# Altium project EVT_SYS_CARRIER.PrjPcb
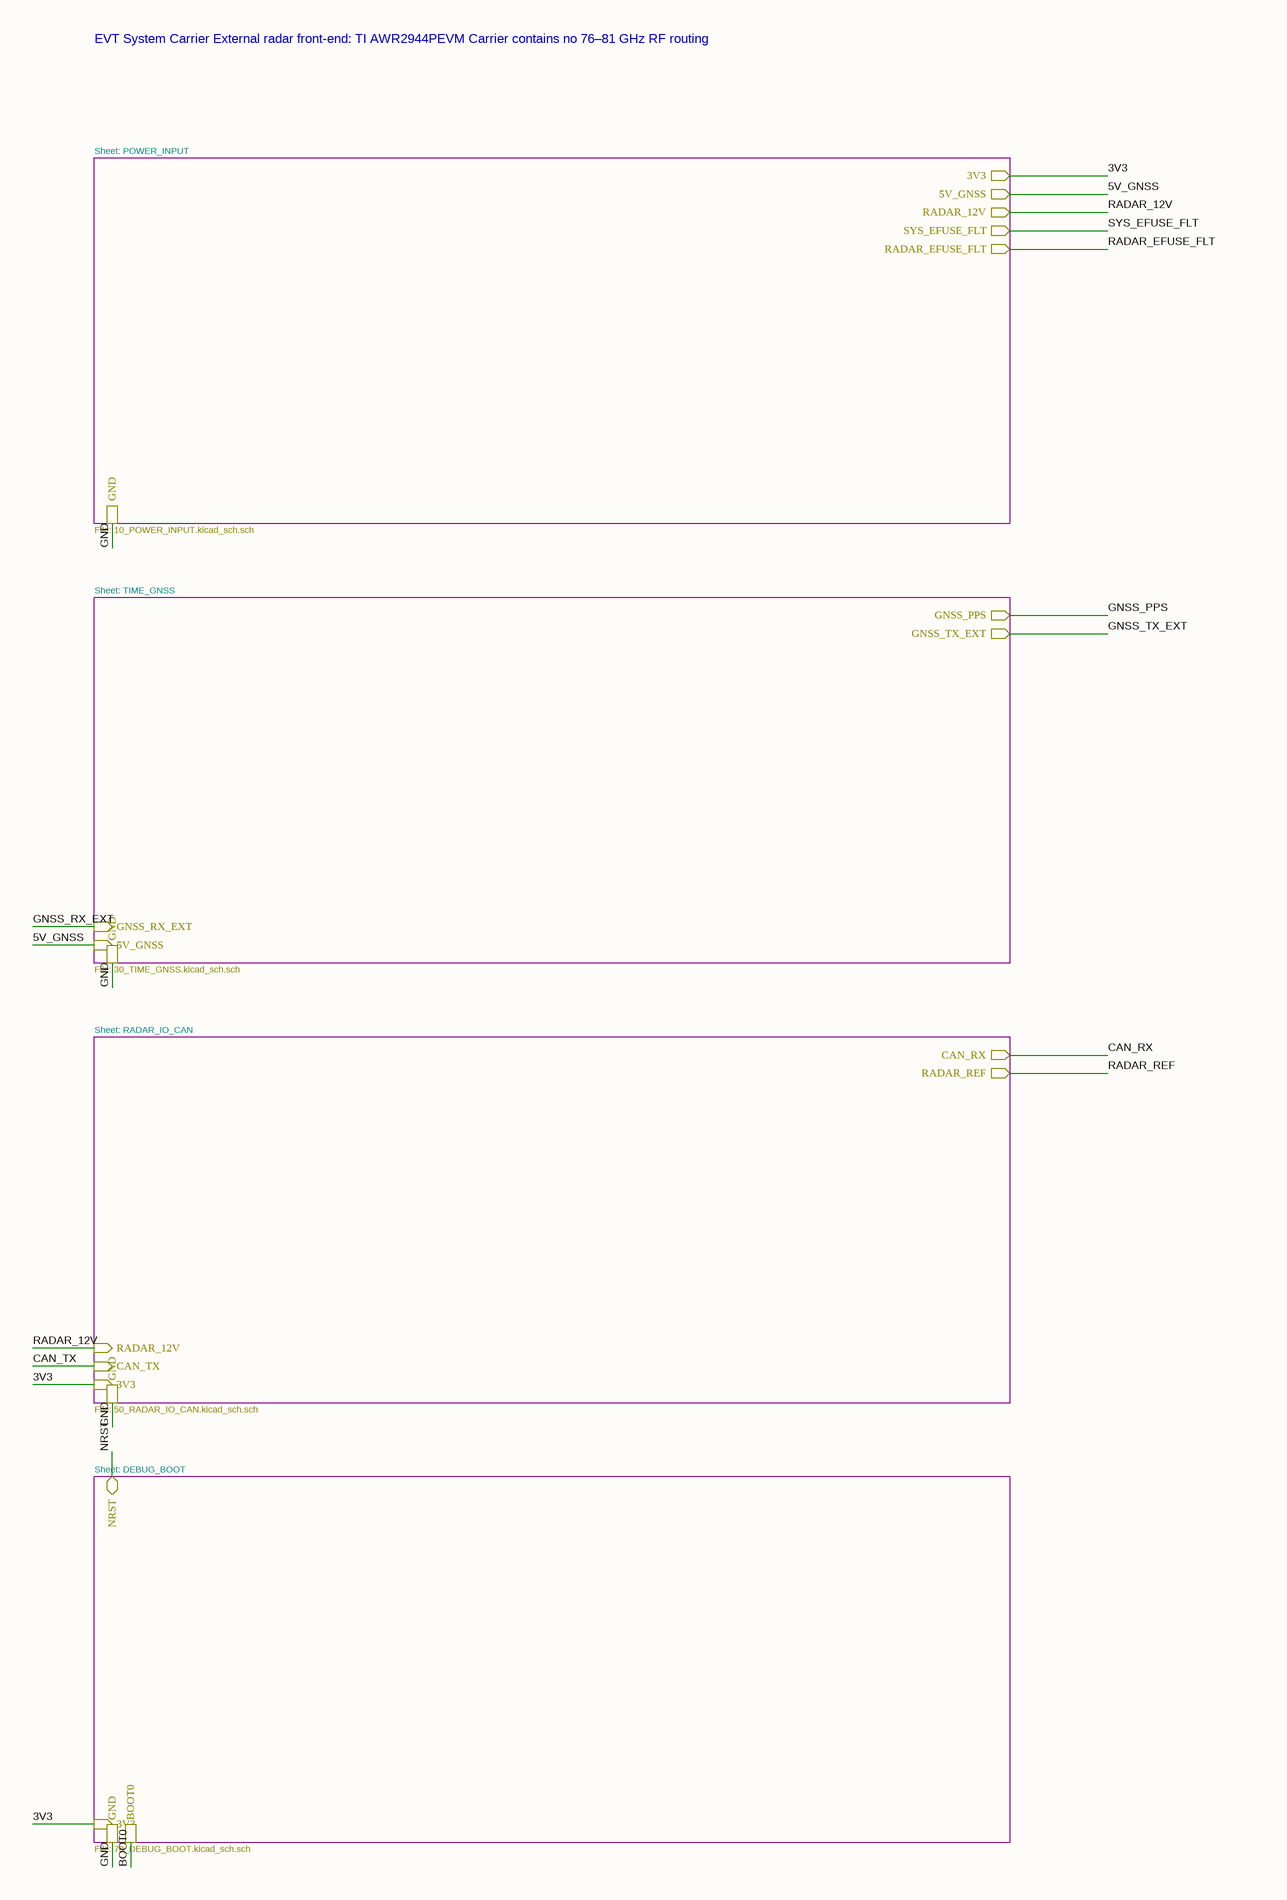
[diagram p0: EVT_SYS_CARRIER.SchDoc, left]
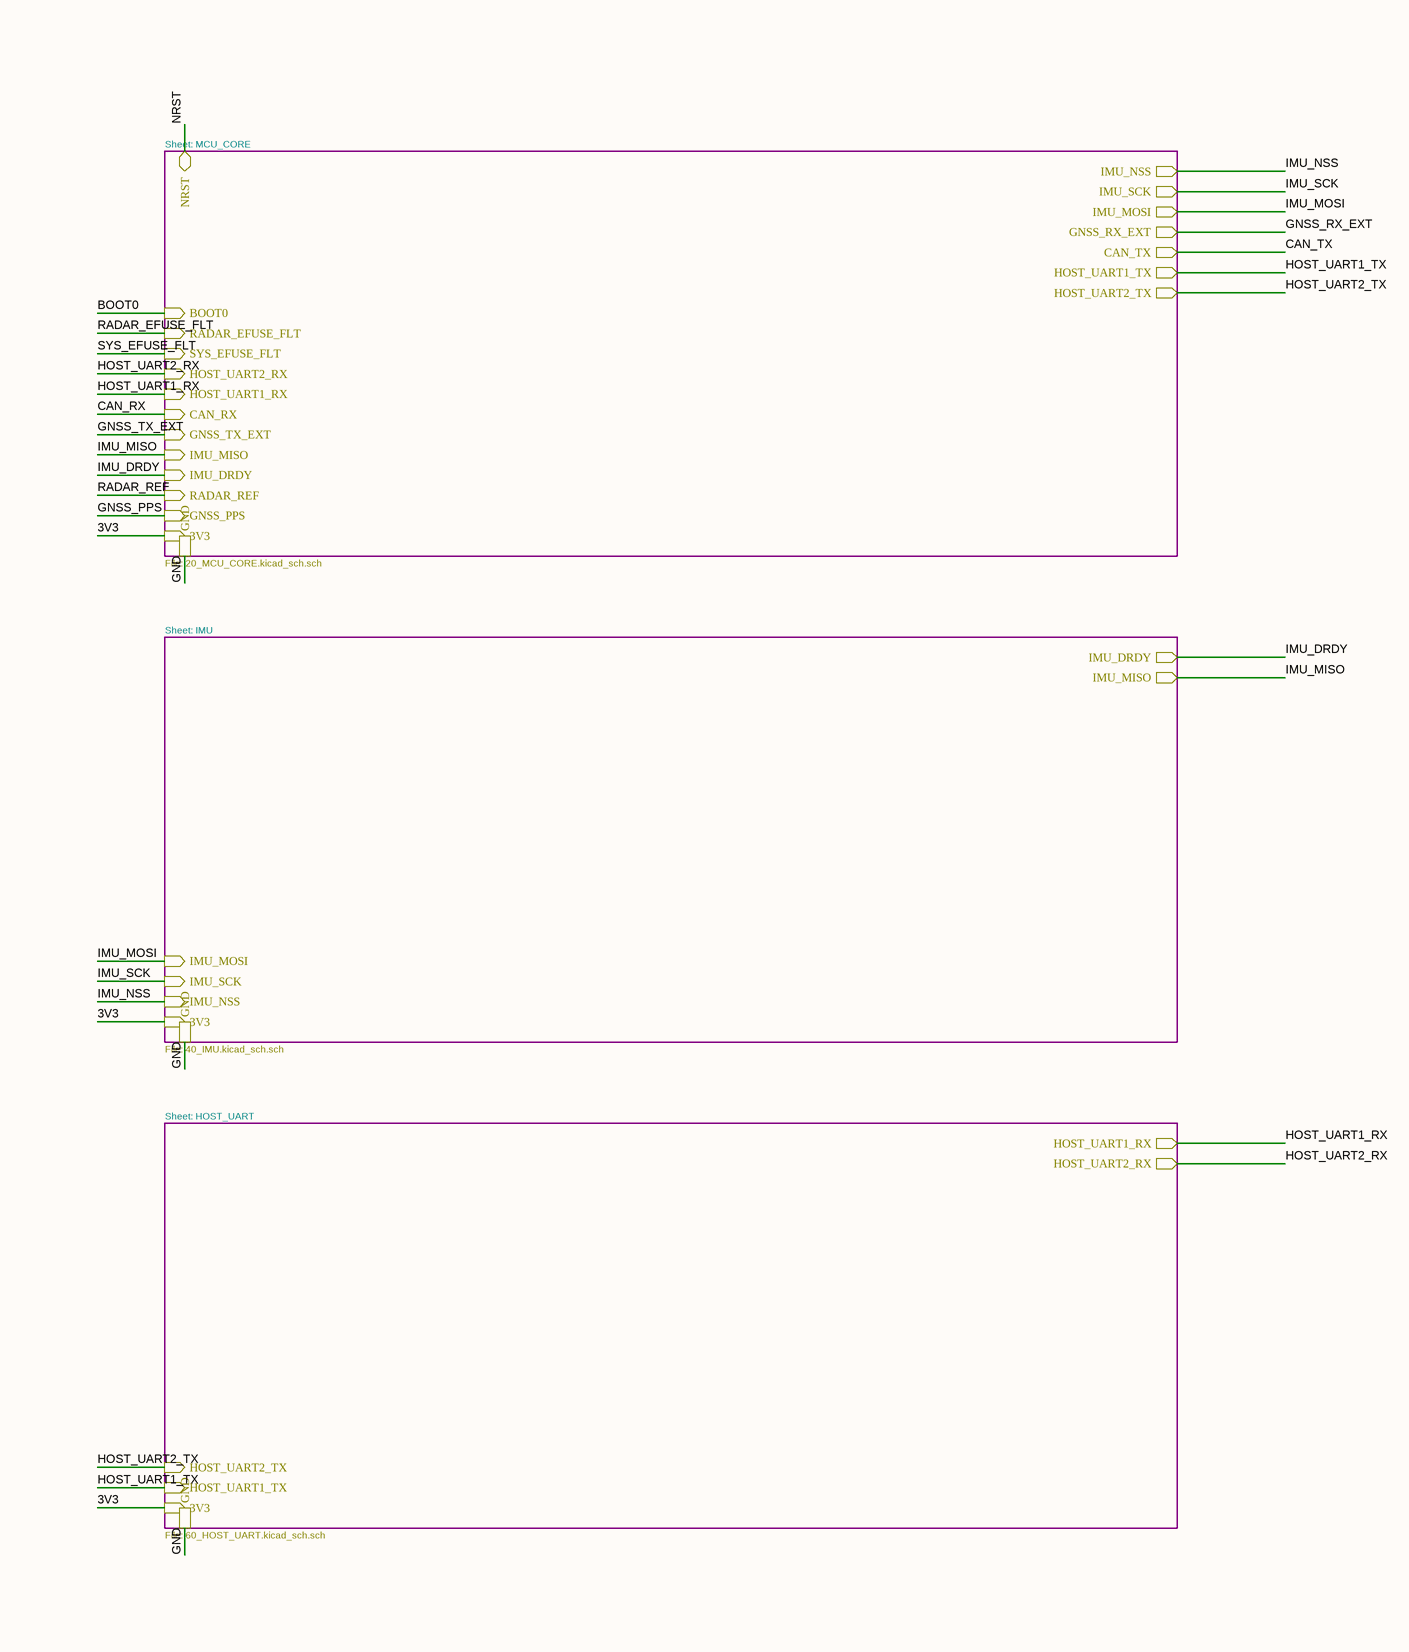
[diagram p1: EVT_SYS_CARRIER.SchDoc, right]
8 sheets, 112 parts. Net scope: hierarchical (ports join the sheet entries above them; power ports are global).
Board file: EVT_SYS_CARRIER.PcbDoc
Sheets:
  EVT_SYS_CARRIER.SchDoc
    POWER_INPUT = 10_POWER_INPUT.SchDoc
    MCU_CORE = 20_MCU_CORE.SchDoc
    TIME_GNSS = 30_TIME_GNSS.SchDoc
    IMU = 40_IMU.SchDoc
    RADAR_IO_CAN = 50_RADAR_IO_CAN.SchDoc
    HOST_UART = 60_HOST_UART.SchDoc
    DEBUG_BOOT = 70_DEBUG_BOOT.SchDoc

## Sheet EVT_SYS_CARRIER.SchDoc
size 594 x 420 mm

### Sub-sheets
DEBUG_BOOT = 70_DEBUG_BOOT.SchDoc: 3V3 (in), GND, NRST (bidir), BOOT0
HOST_UART = 60_HOST_UART.SchDoc: 3V3 (in), GND, HOST_UART1_TX (in), HOST_UART1_RX (out), HOST_UART2_TX (in), HOST_UART2_RX (out)
IMU = 40_IMU.SchDoc: 3V3 (in), GND, IMU_DRDY (out), IMU_NSS (in), IMU_SCK (in), IMU_MISO (out), IMU_MOSI (in)
MCU_CORE = 20_MCU_CORE.SchDoc: 3V3 (in), GND, GNSS_PPS (in), RADAR_REF (in), IMU_DRDY (in), IMU_NSS (out), IMU_SCK (out), IMU_MISO (in), IMU_MOSI (out), GNSS_RX_EXT (out), GNSS_TX_EXT (in), CAN_RX (in), CAN_TX (out), HOST_UART1_TX (out), HOST_UART1_RX (in), HOST_UART2_TX (out), HOST_UART2_RX (in), SYS_EFUSE_FLT (in), RADAR_EFUSE_FLT (in), NRST (bidir), BOOT0 (in)
POWER_INPUT = 10_POWER_INPUT.SchDoc: 3V3 (out), 5V_GNSS (out), RADAR_12V (out), SYS_EFUSE_FLT (out), RADAR_EFUSE_FLT (out), GND
RADAR_IO_CAN = 50_RADAR_IO_CAN.SchDoc: 3V3 (in), GND, CAN_TX (in), CAN_RX (out), RADAR_REF (out), RADAR_12V (in)
TIME_GNSS = 30_TIME_GNSS.SchDoc: 5V_GNSS (in), GND, GNSS_PPS (out), GNSS_TX_EXT (out), GNSS_RX_EXT (in)

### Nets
3V3: sheet POWER_INPUT/3V3, sheet MCU_CORE/3V3, sheet IMU/3V3, sheet RADAR_IO_CAN/3V3, sheet HOST_UART/3V3, sheet DEBUG_BOOT/3V3
5V_GNSS: sheet POWER_INPUT/5V_GNSS, sheet TIME_GNSS/5V_GNSS
BOOT0: sheet MCU_CORE/BOOT0, sheet DEBUG_BOOT/BOOT0
CAN_RX: sheet MCU_CORE/CAN_RX, sheet RADAR_IO_CAN/CAN_RX
CAN_TX: sheet MCU_CORE/CAN_TX, sheet RADAR_IO_CAN/CAN_TX
GND: sheet POWER_INPUT/GND, sheet MCU_CORE/GND, sheet TIME_GNSS/GND, sheet IMU/GND, sheet RADAR_IO_CAN/GND, sheet HOST_UART/GND, sheet DEBUG_BOOT/GND
GNSS_PPS: sheet MCU_CORE/GNSS_PPS, sheet TIME_GNSS/GNSS_PPS
GNSS_RX_EXT: sheet MCU_CORE/GNSS_RX_EXT, sheet TIME_GNSS/GNSS_RX_EXT
GNSS_TX_EXT: sheet MCU_CORE/GNSS_TX_EXT, sheet TIME_GNSS/GNSS_TX_EXT
HOST_UART1_RX: sheet MCU_CORE/HOST_UART1_RX, sheet HOST_UART/HOST_UART1_RX
HOST_UART1_TX: sheet MCU_CORE/HOST_UART1_TX, sheet HOST_UART/HOST_UART1_TX
HOST_UART2_RX: sheet MCU_CORE/HOST_UART2_RX, sheet HOST_UART/HOST_UART2_RX
HOST_UART2_TX: sheet MCU_CORE/HOST_UART2_TX, sheet HOST_UART/HOST_UART2_TX
IMU_DRDY: sheet MCU_CORE/IMU_DRDY, sheet IMU/IMU_DRDY
IMU_MISO: sheet MCU_CORE/IMU_MISO, sheet IMU/IMU_MISO
IMU_MOSI: sheet MCU_CORE/IMU_MOSI, sheet IMU/IMU_MOSI
IMU_NSS: sheet MCU_CORE/IMU_NSS, sheet IMU/IMU_NSS
IMU_SCK: sheet MCU_CORE/IMU_SCK, sheet IMU/IMU_SCK
NRST: sheet MCU_CORE/NRST, sheet DEBUG_BOOT/NRST
RADAR_12V: sheet POWER_INPUT/RADAR_12V, sheet RADAR_IO_CAN/RADAR_12V
RADAR_EFUSE_FLT: sheet POWER_INPUT/RADAR_EFUSE_FLT, sheet MCU_CORE/RADAR_EFUSE_FLT
RADAR_REF: sheet MCU_CORE/RADAR_REF, sheet RADAR_IO_CAN/RADAR_REF
SYS_EFUSE_FLT: sheet POWER_INPUT/SYS_EFUSE_FLT, sheet MCU_CORE/SYS_EFUSE_FLT

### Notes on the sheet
- EVT System Carrier
  External radar front-end: TI AWR2944PEVM
  Carrier contains no 76–81 GHz RF routing
- Sheet: POWER_INPUT
- Sheet: MCU_CORE
- File: 10_POWER_INPUT.kicad_sch.sch
- File: 20_MCU_CORE.kicad_sch.sch
- Sheet: TIME_GNSS
- Sheet: IMU
- File: 30_TIME_GNSS.kicad_sch.sch
- File: 40_IMU.kicad_sch.sch
- Sheet: RADAR_IO_CAN
- Sheet: HOST_UART
- File: 50_RADAR_IO_CAN.kicad_sch.sch
- File: 60_HOST_UART.kicad_sch.sch
- Sheet: DEBUG_BOOT
- File: 70_DEBUG_BOOT.kicad_sch.sch

## Sheet 10_POWER_INPUT.SchDoc
size 420 x 297 mm
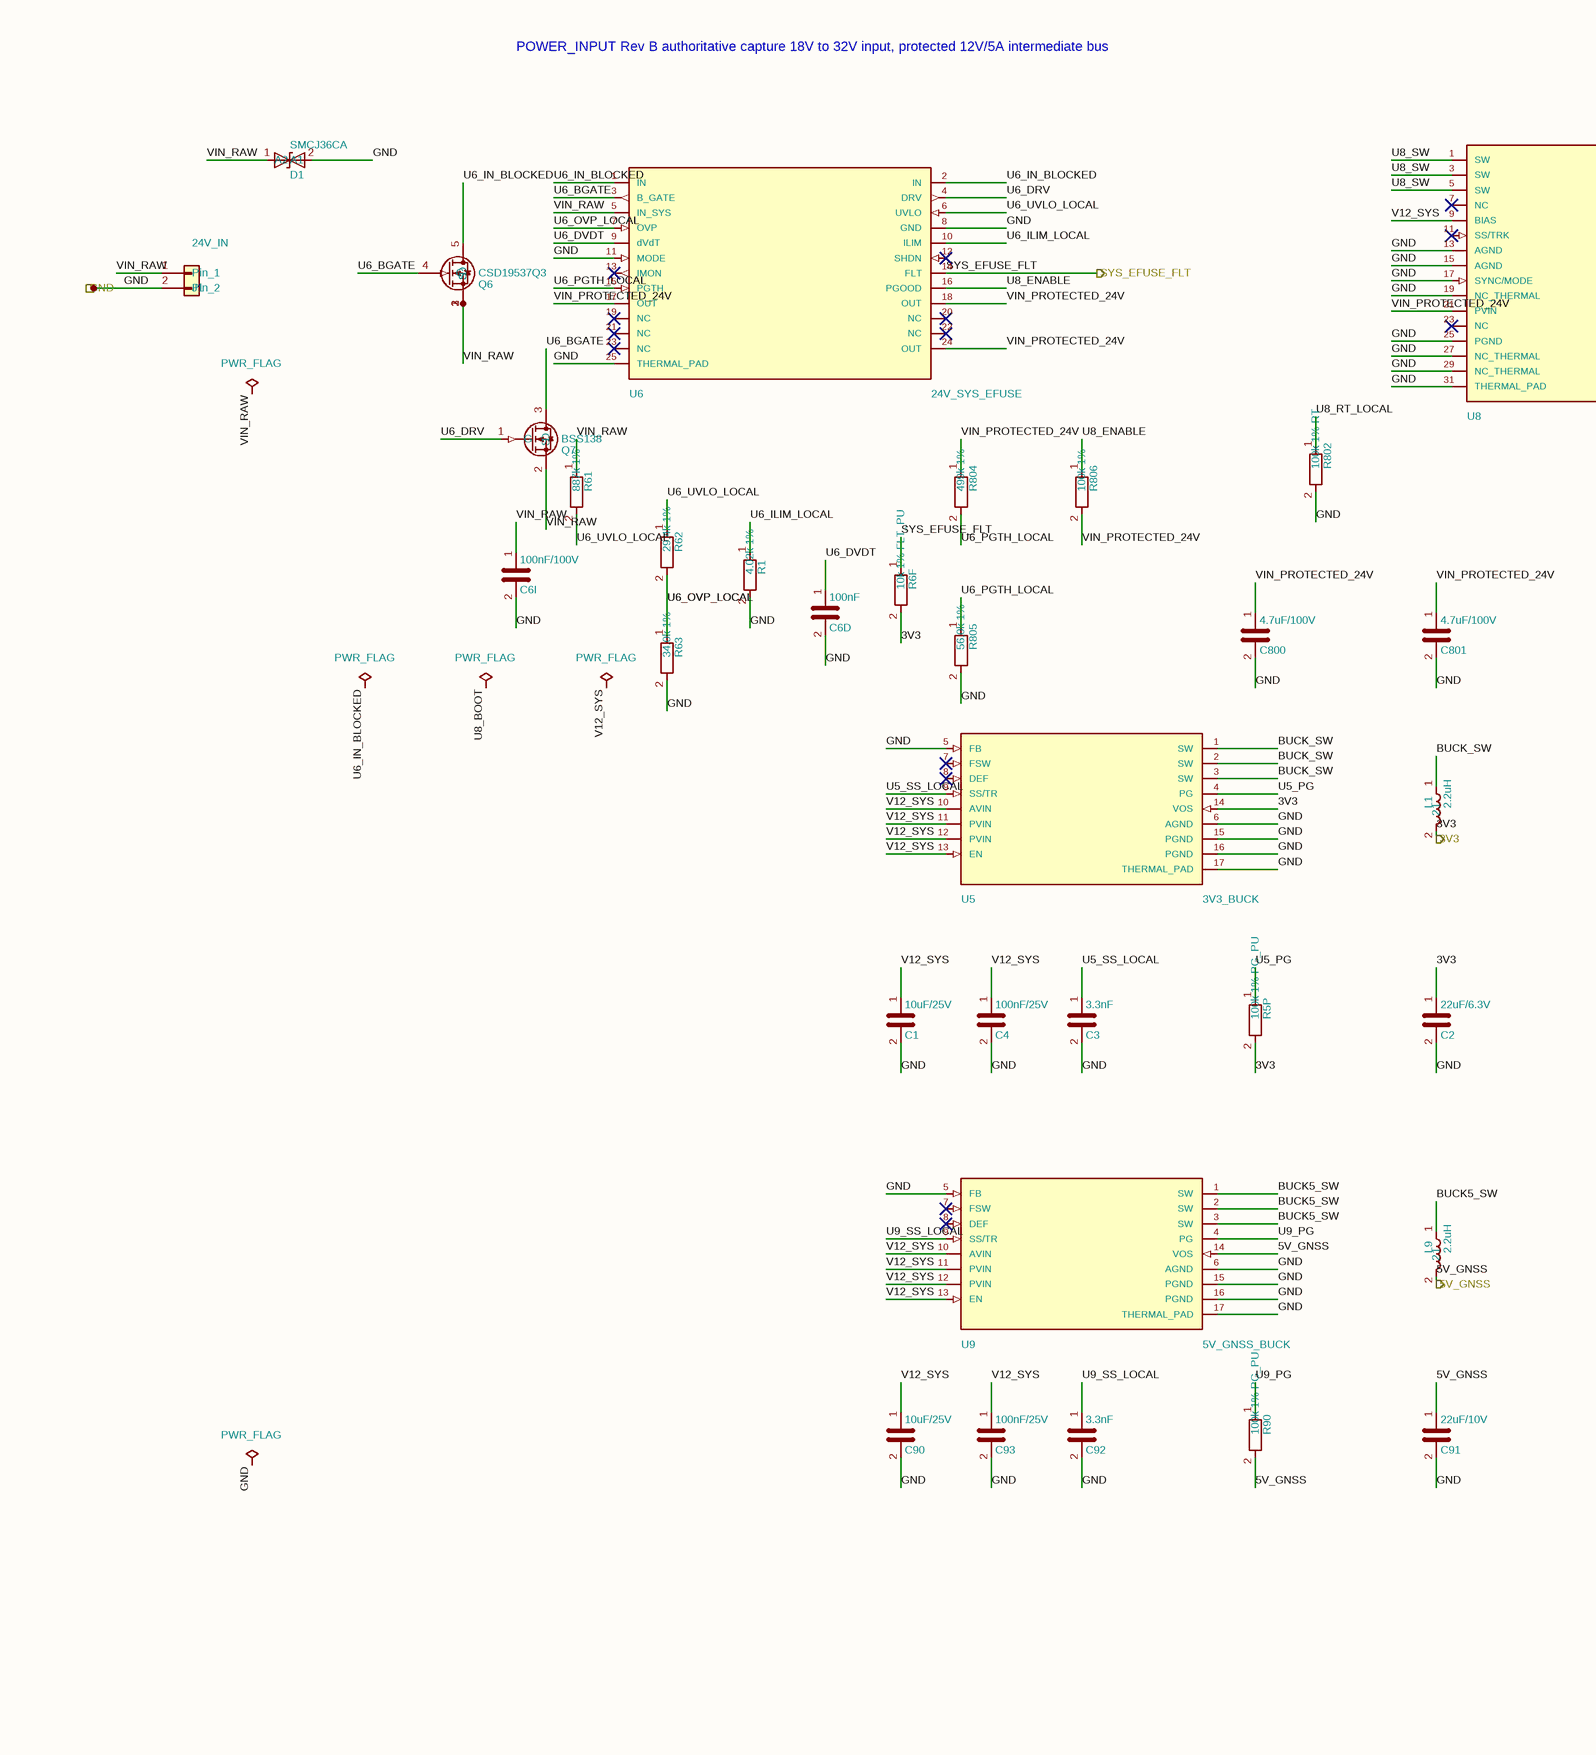
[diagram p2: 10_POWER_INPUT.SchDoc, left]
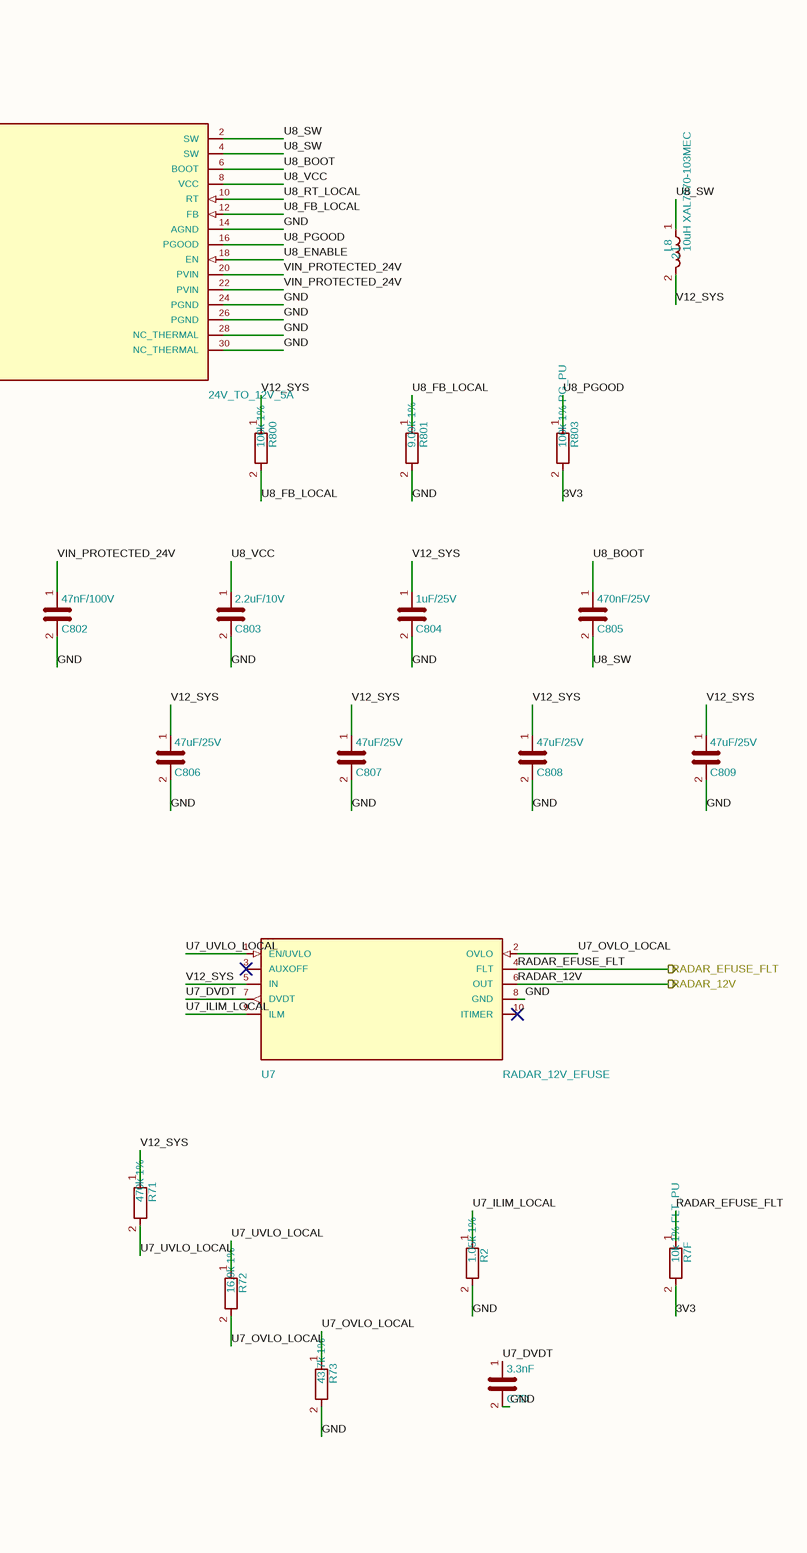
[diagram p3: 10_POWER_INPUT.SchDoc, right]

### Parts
#FLG0201  PWR_FLAG  (graphical)
#FLG0202  PWR_FLAG  (graphical)
#FLG0203  PWR_FLAG  (graphical)
#FLG0204  PWR_FLAG  (graphical)
#FLG0205  PWR_FLAG  (graphical)
C1  10uF/25V  [C_1206_3216Metric]
C2  22uF/6.3V  [C_1206_3216Metric]
C3  3.3nF  [C_0603_1608Metric]
C4  100nF/25V  [C_0603_1608Metric]
C6D  100nF  [C_0603_1608Metric]
C6I  100nF/100V  [C_0603_1608Metric]
C7D  3.3nF  [C_0603_1608Metric]
C90  10uF/25V  [C_1206_3216Metric]
C91  22uF/10V  [C_1206_3216Metric]
C92  3.3nF  [C_0603_1608Metric]
C93  100nF/25V  [C_0603_1608Metric]
C800  4.7uF/100V  [C_1210_3225Metric]
C801  4.7uF/100V  [C_1210_3225Metric]
C802  47nF/100V  [C_0603_1608Metric]
C803  2.2uF/10V  [C_0603_1608Metric]
C804  1uF/25V  [C_0603_1608Metric]
C805  470nF/25V  [C_0603_1608Metric]
C806  47uF/25V  [C_1210_3225Metric]
C807  47uF/25V  [C_1210_3225Metric]
C808  47uF/25V  [C_1210_3225Metric]
C809  47uF/25V  [C_1210_3225Metric]
D1  SMCJ36CA  [D_SMC]
J1  24V_IN  [Molex_43650-0200_RA_THT_2P]
L1  2.2uH  [Coilcraft_XFL4020_4x4]
L8  10uH XAL7070-103MEC  [L_Coilcraft_XAL7070-XXX]
L9  2.2uH  [Coilcraft_XFL4020_4x4]
Q6  CSD19537Q3  [VSON-8_3.3x3.3mm_P0.65mm_NexFET]
Q7  BSS138  [SOT-23]
R1  4.02k 1%  [R_0603_1608Metric]
R2  1.05k 1%  [R_0603_1608Metric]
R5P  100k 1% PG_PU  [R_0603_1608Metric]
R6F  10k 1% FLT_PU  [R_0603_1608Metric]
R7F  10k 1% FLT_PU  [R_0603_1608Metric]
R61  887k 1%  [R_0603_1608Metric]
R62  29.4k 1%  [R_0603_1608Metric]
R63  34.0k 1%  [R_0603_1608Metric]
R71  470k 1%  [R_0603_1608Metric]
R72  16.9k 1%  [R_0603_1608Metric]
R73  43.7k 1%  [R_0603_1608Metric]
R90  100k 1% PG_PU  [R_0603_1608Metric]
R800  100k 1%  [R_0603_1608Metric]
R801  9.09k 1%  [R_0603_1608Metric]
R802  100k 1% RT  [R_0603_1608Metric]
R803  100k 1% PG_PU  [R_0603_1608Metric]
R804  499k 1%  [R_0603_1608Metric]
R805  56.0k 1%  [R_0603_1608Metric]
R806  100k 1%  [R_0603_1608Metric]
U5  3V3_BUCK  [VQFN-16-1EP_3x3mm_P0.5mm_EP1.68x1.68mm]
U6  24V_SYS_EFUSE  [Texas_RGE0024C_VQFN-24-1EP_4x4mm_P0.5mm_EP2.1x2.1mm]
U7  RADAR_12V_EFUSE  [TPS259470A_RPW0010A_VQFN-HR-10_2x2mm_P0.475mm]
U8  24V_TO_12V_5A  [Texas_RNP0030B_WQFN-30-1EP_4x6mm_P0.5mm_EP1.8x4.5mm_ThermalVias]
U9  5V_GNSS_BUCK  [VQFN-16-1EP_3x3mm_P0.5mm_EP1.68x1.68mm]

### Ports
3V3 (out), 5V_GNSS (out), GND, RADAR_12V (out), RADAR_EFUSE_FLT (out), SYS_EFUSE_FLT (out)

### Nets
3V3: C2.1 L1.2 R5P.2 R6F.2 R7F.2 R803.2 U5.14(VOS) ; port 3V3
5V_GNSS: C91.1 L9.2 R90.2 U9.14(VOS) ; port 5V_GNSS
BUCK5_SW: L9.1 U9.1(SW) U9.2(SW) U9.3(SW)
BUCK_SW: L1.1 U5.1(SW) U5.2(SW) U5.3(SW)
GND: #FLG0202.1 C1.2 C2.2 C3.2 C4.2 C6D.2 C6I.2 C7D.2 C90.2 C91.2 C92.2 C93.2 C800.2 C801.2 C802.2 C803.2 C804.2 C806.2 C807.2 C808.2 C809.2 D1.2(A2) J1.2(Pin_2) R1.2 R2.2 R63.2 R73.2 R801.2 R802.2 R805.2 U5.5(FB) U5.6(AGND) U5.15(PGND) U5.16(PGND) U5.17(THERMAL_PAD) U6.8(GND) U6.11(MODE) U6.25(THERMAL_PAD) U7.8(GND) U8.13(AGND) U8.14(AGND) U8.15(AGND) U8.17(SYNC/MODE) U8.19(NC_THERMAL) U8.24(PGND) U8.25(PGND) U8.26(PGND) U8.27(NC_THERMAL) U8.28(NC_THERMAL) U8.29(NC_THERMAL) U8.30(NC_THERMAL) U8.31(THERMAL_PAD) U9.5(FB) U9.6(AGND) U9.15(PGND) U9.16(PGND) U9.17(THERMAL_PAD) ; port GND
RADAR_12V: U7.6(OUT) ; port RADAR_12V
RADAR_EFUSE_FLT: R7F.1 U7.4(FLT) ; port RADAR_EFUSE_FLT
SYS_EFUSE_FLT: R6F.1 U6.14(FLT) ; port SYS_EFUSE_FLT
U5_PG: R5P.1 U5.4(PG)
U5_SS_LOCAL: C3.1 U5.9(SS/TR)
U6_BGATE: Q6.4(G) Q7.3(D) U6.3(B_GATE)
U6_DRV: Q7.1(G) U6.4(DRV)
U6_DVDT: C6D.1 U6.9(dVdT)
U6_ILIM_LOCAL: R1.1 U6.10(ILIM)
U6_IN_BLOCKED: #FLG0203.1 Q6.5(D) U6.1(IN) U6.2(IN)
U6_OVP_LOCAL: R62.2 R63.1 U6.7(OVP)
U6_PGTH_LOCAL: R804.2 R805.1 U6.15(PGTH)
U6_UVLO_LOCAL: R61.2 R62.1 U6.6(UVLO)
U7_DVDT: C7D.1 U7.7(DVDT)
U7_ILIM_LOCAL: R2.1 U7.9(ILM)
U7_OVLO_LOCAL: R72.2 R73.1 U7.2(OVLO)
U7_UVLO_LOCAL: R71.2 R72.1 U7.1(EN/UVLO)
U8_BOOT: #FLG0204.1 C805.1 U8.6(BOOT)
U8_ENABLE: R806.1 U6.16(PGOOD) U8.18(EN)
U8_FB_LOCAL: R800.2 R801.1 U8.12(FB)
U8_PGOOD: R803.1 U8.16(PGOOD)
U8_RT_LOCAL: R802.1 U8.10(RT)
U8_SW: C805.2 L8.1 U8.1(SW) U8.2(SW) U8.3(SW) U8.4(SW) U8.5(SW)
U8_VCC: C803.1 U8.8(VCC)
U9_PG: R90.1 U9.4(PG)
U9_SS_LOCAL: C92.1 U9.9(SS/TR)
V12_SYS: #FLG0205.1 C1.1 C4.1 C90.1 C93.1 C804.1 C806.1 C807.1 C808.1 C809.1 L8.2 R71.1 R800.1 U5.10(AVIN) U5.11(PVIN) U5.12(PVIN) U5.13(EN) U7.5(IN) U8.9(BIAS) U9.10(AVIN) U9.11(PVIN) U9.12(PVIN) U9.13(EN)
VIN_PROTECTED_24V: C800.1 C801.1 C802.1 R804.1 R806.2 U6.17(OUT) U6.18(OUT) U6.24(OUT) U8.20(PVIN) U8.21(PVIN) U8.22(PVIN)
VIN_RAW: #FLG0201.1 C6I.1 D1.1(A1) J1.1(Pin_1) Q6.1(S) Q6.2(S) Q6.3(S) Q7.2(S) R61.1 U6.5(IN_SYS)

Not connected (* = marked no-connect by the designer): U5 7(FSW)* 8(DEF)*; U6 12(SHDN)* 13(IMON)* 19(NC)* 20(NC)* 21(NC)* 22(NC)* 23(NC)*; U7 3(AUXOFF)* 10(ITIMER)*; U8 7(NC)* 11(SS/TRK)* 23(NC)*; U9 7(FSW)* 8(DEF)*

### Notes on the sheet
- POWER_INPUT Rev B authoritative capture
  18V to 32V input, protected 12V/5A intermediate bus

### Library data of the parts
#FLG0201 #FLG0202 #FLG0203 #FLG0204 #FLG0205 = PWR_FLAG: hierarchy_path: /66980d89-56fb-4772-93a7-06a61d388399/6dd53468-99c2-4197-8bec-3687fb851dcd
C1 C90 = C: MPN: 10uF_25V_X7R; hierarchy_path: /66980d89-56fb-4772-93a7-06a61d388399/6dd53468-99c2-4197-8bec-3687fb851dcd
C2 = C: MPN: 22uF_6.3V_X7R; hierarchy_path: /66980d89-56fb-4772-93a7-06a61d388399/6dd53468-99c2-4197-8bec-3687fb851dcd
C3 C7D C92 = C: MPN: 3.3nF_X7R; hierarchy_path: /66980d89-56fb-4772-93a7-06a61d388399/6dd53468-99c2-4197-8bec-3687fb851dcd
C4 C6D C93 = C: MPN: 100nF_25V_X7R; hierarchy_path: /66980d89-56fb-4772-93a7-06a61d388399/6dd53468-99c2-4197-8bec-3687fb851dcd
C6I = C: MPN: 100nF_100V_X7R; hierarchy_path: /66980d89-56fb-4772-93a7-06a61d388399/6dd53468-99c2-4197-8bec-3687fb851dcd
C91 = C: MPN: 22uF_10V_X7R; hierarchy_path: /66980d89-56fb-4772-93a7-06a61d388399/6dd53468-99c2-4197-8bec-3687fb851dcd
C800 C801 = C: MPN: C3225X7S2A475K200AB; hierarchy_path: /66980d89-56fb-4772-93a7-06a61d388399/6dd53468-99c2-4197-8bec-3687fb851dcd
C802 = C: MPN: 47nF_100V_X7R; hierarchy_path: /66980d89-56fb-4772-93a7-06a61d388399/6dd53468-99c2-4197-8bec-3687fb851dcd
C803 = C: MPN: 2.2uF_10V_X7R; hierarchy_path: /66980d89-56fb-4772-93a7-06a61d388399/6dd53468-99c2-4197-8bec-3687fb851dcd
C804 = C: MPN: 1uF_25V_X7R; hierarchy_path: /66980d89-56fb-4772-93a7-06a61d388399/6dd53468-99c2-4197-8bec-3687fb851dcd
C805 = C: MPN: 470nF_25V_X7R; hierarchy_path: /66980d89-56fb-4772-93a7-06a61d388399/6dd53468-99c2-4197-8bec-3687fb851dcd
C806-C809 = C: MPN: 47uF_25V_X7R; hierarchy_path: /66980d89-56fb-4772-93a7-06a61d388399/6dd53468-99c2-4197-8bec-3687fb851dcd
D1 = D_TVS: hierarchy_path: /66980d89-56fb-4772-93a7-06a61d388399/6dd53468-99c2-4197-8bec-3687fb851dcd
J1 = Conn_01x02: MPN: 43650-0200; hierarchy_path: /66980d89-56fb-4772-93a7-06a61d388399/6dd53468-99c2-4197-8bec-3687fb851dcd
L1 L9 = L: MPN: XFL4020-222MEC; hierarchy_path: /66980d89-56fb-4772-93a7-06a61d388399/6dd53468-99c2-4197-8bec-3687fb851dcd
L8 = L: hierarchy_path: /66980d89-56fb-4772-93a7-06a61d388399/6dd53468-99c2-4197-8bec-3687fb851dcd
Q6 = CSD19537Q3: hierarchy_path: /66980d89-56fb-4772-93a7-06a61d388399/6dd53468-99c2-4197-8bec-3687fb851dcd
Q7 = BSS138: hierarchy_path: /66980d89-56fb-4772-93a7-06a61d388399/6dd53468-99c2-4197-8bec-3687fb851dcd
R1 = R: MPN: 4.02k_1%; hierarchy_path: /66980d89-56fb-4772-93a7-06a61d388399/6dd53468-99c2-4197-8bec-3687fb851dcd
R2 = R: MPN: 1.05k_1%; hierarchy_path: /66980d89-56fb-4772-93a7-06a61d388399/6dd53468-99c2-4197-8bec-3687fb851dcd
R5P R90 R800 R802 R803 R806 = R: MPN: 100k_1%; hierarchy_path: /66980d89-56fb-4772-93a7-06a61d388399/6dd53468-99c2-4197-8bec-3687fb851dcd
R6F R7F = R: MPN: 10k_1%; hierarchy_path: /66980d89-56fb-4772-93a7-06a61d388399/6dd53468-99c2-4197-8bec-3687fb851dcd
R61 = R: MPN: 887k_1%; hierarchy_path: /66980d89-56fb-4772-93a7-06a61d388399/6dd53468-99c2-4197-8bec-3687fb851dcd
R62 = R: MPN: 29.4k_1%; hierarchy_path: /66980d89-56fb-4772-93a7-06a61d388399/6dd53468-99c2-4197-8bec-3687fb851dcd
R63 = R: MPN: 34.0k_1%; hierarchy_path: /66980d89-56fb-4772-93a7-06a61d388399/6dd53468-99c2-4197-8bec-3687fb851dcd
R71 = R: MPN: 470k_1%; hierarchy_path: /66980d89-56fb-4772-93a7-06a61d388399/6dd53468-99c2-4197-8bec-3687fb851dcd
R72 = R: MPN: 16.9k_1%; hierarchy_path: /66980d89-56fb-4772-93a7-06a61d388399/6dd53468-99c2-4197-8bec-3687fb851dcd
R73 = R: MPN: 43.7k_1%; hierarchy_path: /66980d89-56fb-4772-93a7-06a61d388399/6dd53468-99c2-4197-8bec-3687fb851dcd
R801 = R: MPN: 9.09k_1%; hierarchy_path: /66980d89-56fb-4772-93a7-06a61d388399/6dd53468-99c2-4197-8bec-3687fb851dcd
R804 = R: MPN: 499k_1%; hierarchy_path: /66980d89-56fb-4772-93a7-06a61d388399/6dd53468-99c2-4197-8bec-3687fb851dcd
R805 = R: MPN: 56.0k_1%; hierarchy_path: /66980d89-56fb-4772-93a7-06a61d388399/6dd53468-99c2-4197-8bec-3687fb851dcd
U5 = TPS62132RGTR: Capture_Status: LOCAL_CONTRACT_SYMBOL; hierarchy_path: /66980d89-56fb-4772-93a7-06a61d388399/6dd53468-99c2-4197-8bec-3687fb851dcd
U6 = TPS26630RGER: Capture_Status: LOCAL_CONTRACT_SYMBOL; hierarchy_path: /66980d89-56fb-4772-93a7-06a61d388399/6dd53468-99c2-4197-8bec-3687fb851dcd
U7 = TPS259470ARPWR: Capture_Status: LOCAL_CONTRACT_SYMBOL; hierarchy_path: /66980d89-56fb-4772-93a7-06a61d388399/6dd53468-99c2-4197-8bec-3687fb851dcd
U8 = LM76005RNPR: Capture_Status: LOCAL_CONTRACT_SYMBOL; hierarchy_path: /66980d89-56fb-4772-93a7-06a61d388399/6dd53468-99c2-4197-8bec-3687fb851dcd
U9 = TPS62133RGTR: Capture_Status: LOCAL_CONTRACT_SYMBOL; hierarchy_path: /66980d89-56fb-4772-93a7-06a61d388399/6dd53468-99c2-4197-8bec-3687fb851dcd

## Sheet 20_MCU_CORE.SchDoc
size 420 x 297 mm
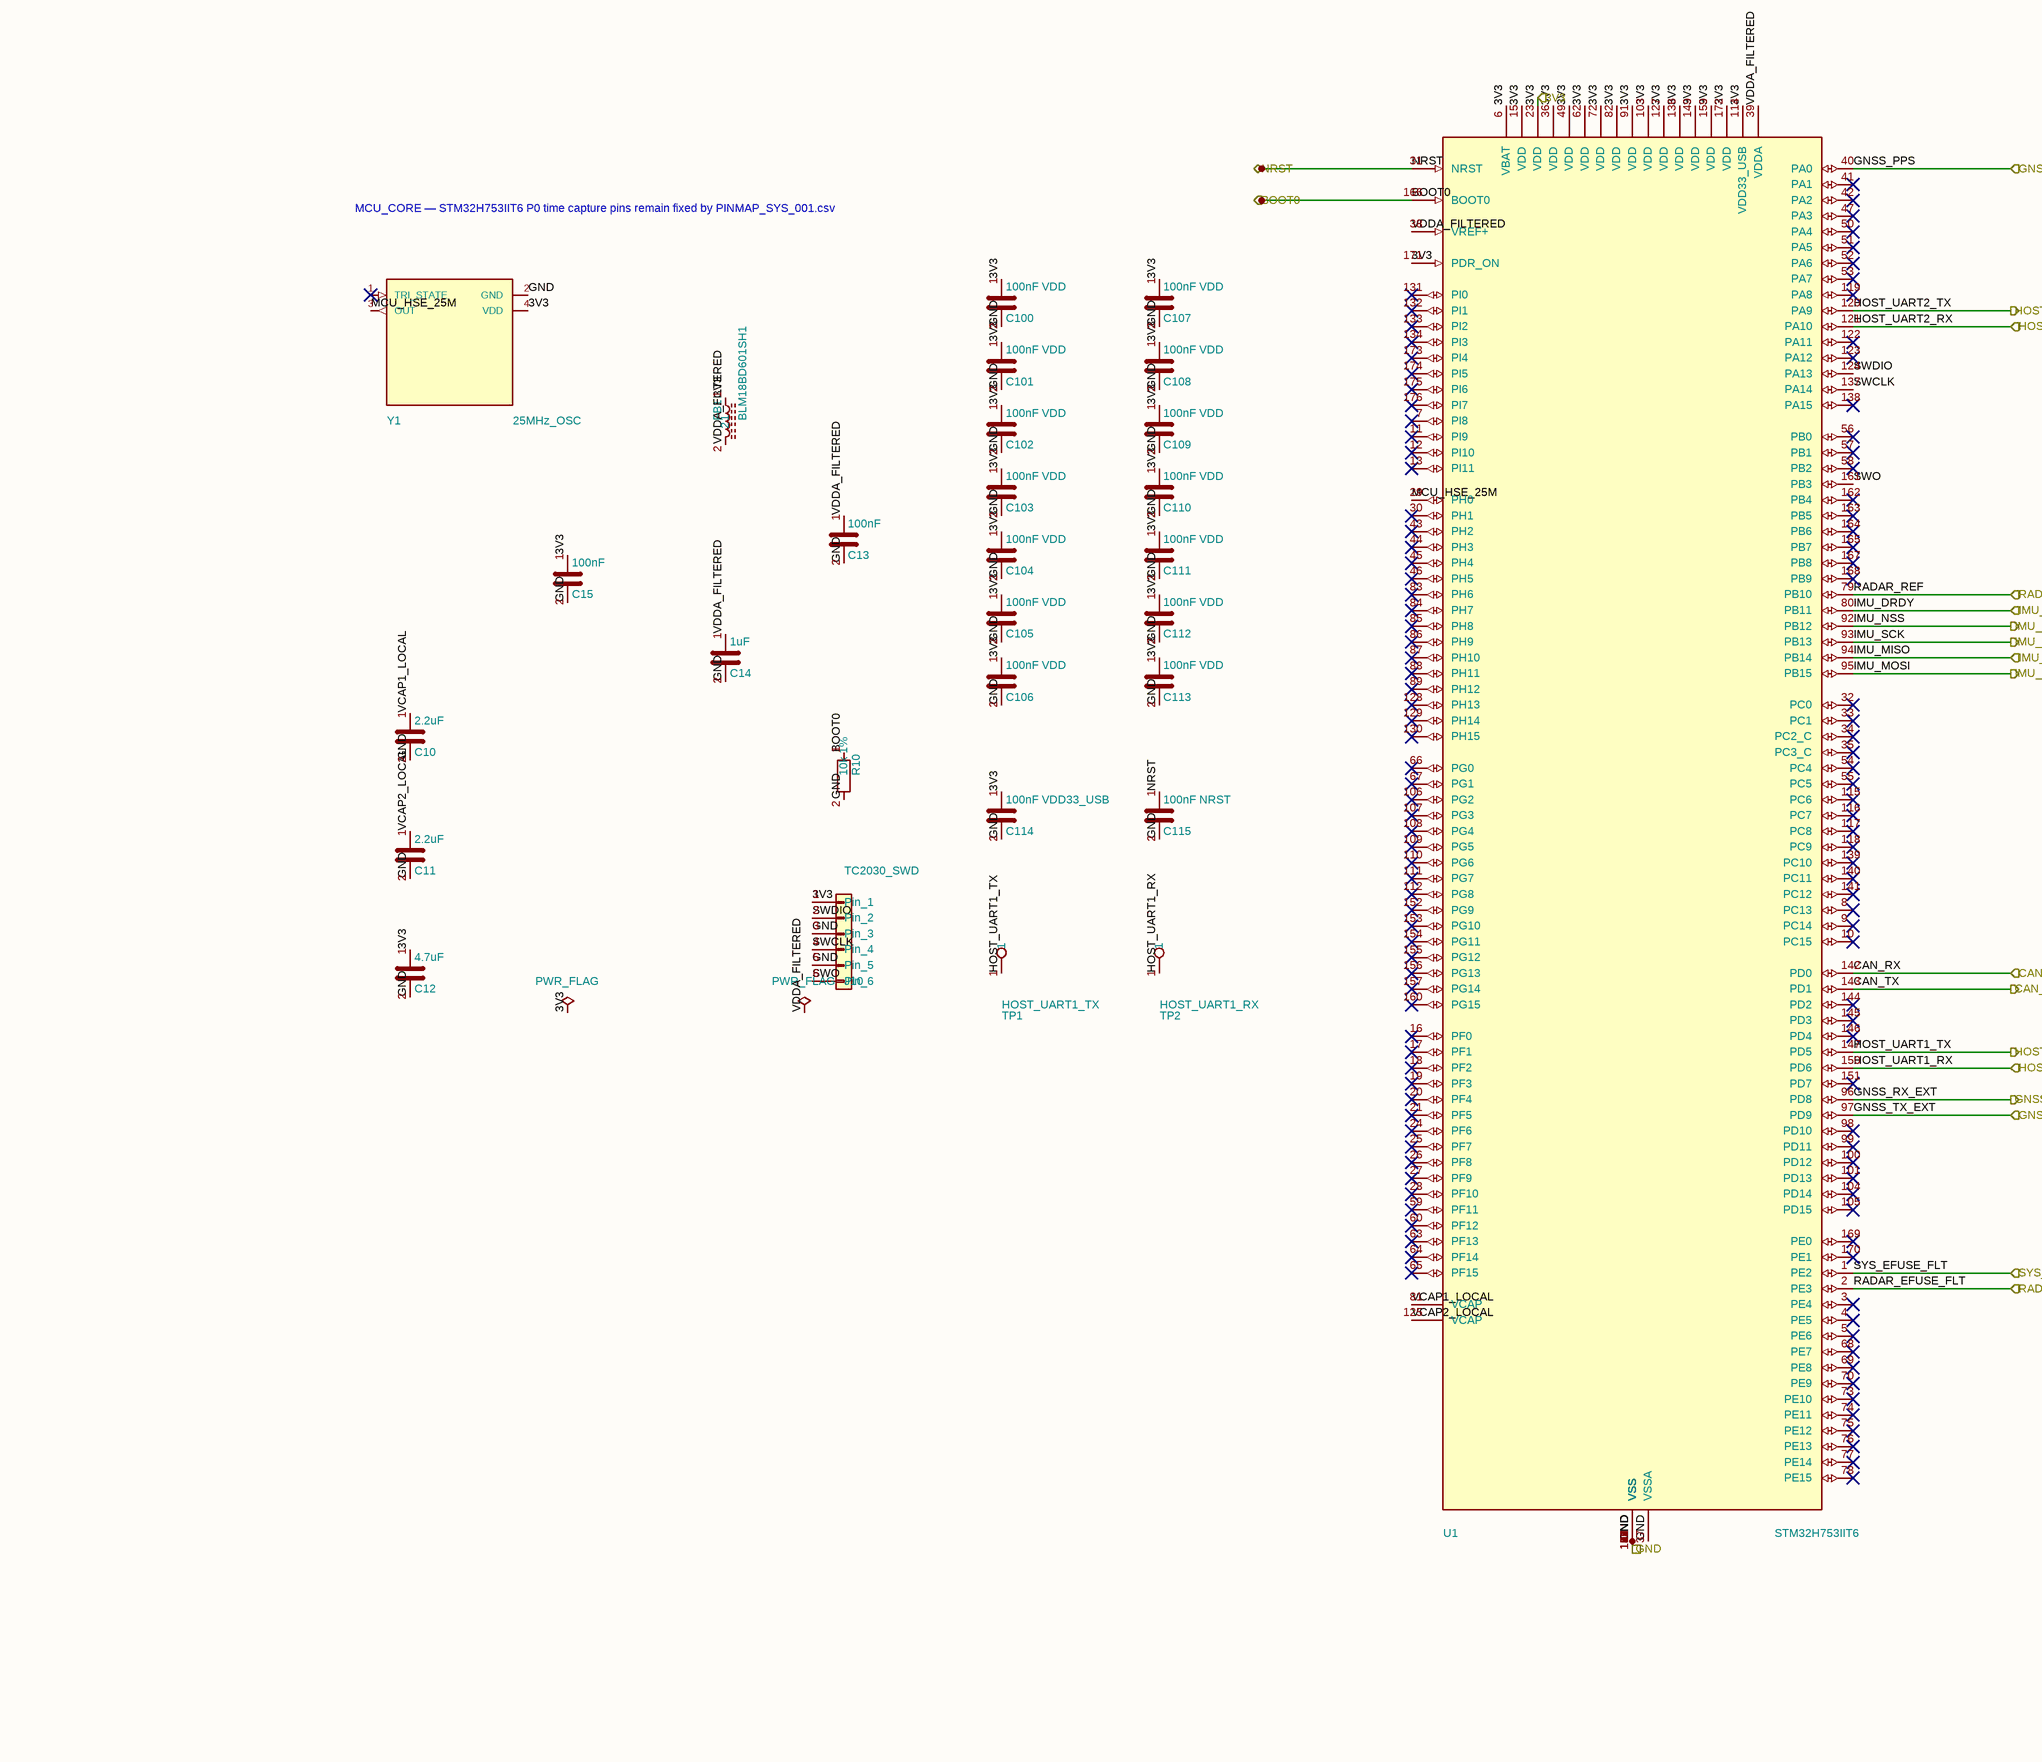
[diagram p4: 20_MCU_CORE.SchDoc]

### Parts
#FLG0101  PWR_FLAG  (graphical)
#FLG0103  PWR_FLAG  (graphical)
C10  2.2uF  [C_0603_1608Metric]
C11  2.2uF  [C_0603_1608Metric]
C12  4.7uF  [C_0805_2012Metric]
C13  100nF  [C_0402_1005Metric]
C14  1uF  [C_0603_1608Metric]
C15  100nF  [C_0402_1005Metric]
C100  100nF VDD  [C_0402_1005Metric]
C101  100nF VDD  [C_0402_1005Metric]
C102  100nF VDD  [C_0402_1005Metric]
C103  100nF VDD  [C_0402_1005Metric]
C104  100nF VDD  [C_0402_1005Metric]
C105  100nF VDD  [C_0402_1005Metric]
C106  100nF VDD  [C_0402_1005Metric]
C107  100nF VDD  [C_0402_1005Metric]
C108  100nF VDD  [C_0402_1005Metric]
C109  100nF VDD  [C_0402_1005Metric]
C110  100nF VDD  [C_0402_1005Metric]
C111  100nF VDD  [C_0402_1005Metric]
C112  100nF VDD  [C_0402_1005Metric]
C113  100nF VDD  [C_0402_1005Metric]
C114  100nF VDD33_USB  [C_0402_1005Metric]
C115  100nF NRST  [C_0402_1005Metric]
FB1  BLM18BD601SH1  [L_0603_1608Metric]
J10  TC2030_SWD  [TagConnect_TC2030_NL]
R10  10k 1%  [R_0603_1608Metric]
TP1  HOST_UART1_TX  [TestPoint_Pad_D1.0mm]
TP2  HOST_UART1_RX  [TestPoint_Pad_D1.0mm]
U1  STM32H753IIT6  [LQFP-176_24x24mm_P0.5mm]
Y1  25MHz_OSC  [Oscillator_SMD_ECS_2520MV-xxx-xx-4Pin_2.5x2.0mm]

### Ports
3V3 (in), BOOT0 (in), CAN_RX (in), CAN_TX (out), GND, GNSS_PPS (in), GNSS_RX_EXT (out), GNSS_TX_EXT (in), HOST_UART1_RX (in), HOST_UART1_TX (out), HOST_UART2_RX (in), HOST_UART2_TX (out), IMU_DRDY (in), IMU_MISO (in), IMU_MOSI (out), IMU_NSS (out), IMU_SCK (out), NRST (bidir), RADAR_EFUSE_FLT (in), RADAR_REF (in), SYS_EFUSE_FLT (in)

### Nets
3V3: #FLG0101.1 C12.1 C15.1 C100.1 C101.1 C102.1 C103.1 C104.1 C105.1 C106.1 C107.1 C108.1 C109.1 C110.1 C111.1 C112.1 C113.1 C114.1 FB1.1 J10.1(Pin_1) U1.6(VBAT) U1.15(VDD) U1.23(VDD) U1.36(VDD) U1.49(VDD) U1.62(VDD) U1.72(VDD) U1.82(VDD) U1.91(VDD) U1.103(VDD) U1.114(VDD33_USB) U1.127(VDD) U1.136(VDD) U1.149(VDD) U1.159(VDD) U1.171(PDR_ON) U1.172(VDD) Y1.4(VDD) ; port 3V3
BOOT0: R10.1 U1.166(BOOT0) ; port BOOT0
CAN_RX: U1.142(PD0) ; port CAN_RX
CAN_TX: U1.143(PD1) ; port CAN_TX
GND: C10.2 C11.2 C12.2 C13.2 C14.2 C15.2 C100.2 C101.2 C102.2 C103.2 C104.2 C105.2 C106.2 C107.2 C108.2 C109.2 C110.2 C111.2 C112.2 C113.2 C114.2 C115.2 J10.3(Pin_3) J10.5(Pin_5) R10.2 U1.14(VSS) U1.22(VSS) U1.37(VSSA) U1.48(VSS) U1.61(VSS) U1.71(VSS) U1.90(VSS) U1.102(VSS) U1.113(VSS) U1.126(VSS) U1.135(VSS) U1.148(VSS) U1.158(VSS) Y1.2(GND) ; port GND
GNSS_PPS: U1.40(PA0) ; port GNSS_PPS
GNSS_RX_EXT: U1.96(PD8) ; port GNSS_RX_EXT
GNSS_TX_EXT: U1.97(PD9) ; port GNSS_TX_EXT
HOST_UART1_RX: TP2.1 U1.150(PD6) ; port HOST_UART1_RX
HOST_UART1_TX: TP1.1 U1.147(PD5) ; port HOST_UART1_TX
HOST_UART2_RX: U1.121(PA10) ; port HOST_UART2_RX
HOST_UART2_TX: U1.120(PA9) ; port HOST_UART2_TX
IMU_DRDY: U1.80(PB11) ; port IMU_DRDY
IMU_MISO: U1.94(PB14) ; port IMU_MISO
IMU_MOSI: U1.95(PB15) ; port IMU_MOSI
IMU_NSS: U1.92(PB12) ; port IMU_NSS
IMU_SCK: U1.93(PB13) ; port IMU_SCK
MCU_HSE_25M: U1.29(PH0) Y1.3(OUT)
NRST: C115.1 U1.31(NRST) ; port NRST
RADAR_EFUSE_FLT: U1.2(PE3) ; port RADAR_EFUSE_FLT
RADAR_REF: U1.79(PB10) ; port RADAR_REF
SWCLK: J10.4(Pin_4) U1.137(PA14)
SWDIO: J10.2(Pin_2) U1.124(PA13)
SWO: J10.6(Pin_6) U1.161(PB3)
SYS_EFUSE_FLT: U1.1(PE2) ; port SYS_EFUSE_FLT
VCAP1_LOCAL: C10.1 U1.81(VCAP)
VCAP2_LOCAL: C11.1 U1.125(VCAP)
VDDA_FILTERED: #FLG0103.1 C13.1 C14.1 FB1.2 U1.38(VREF+) U1.39(VDDA)

Not connected (* = marked no-connect by the designer): U1 3(PE4)* 4(PE5)* 5(PE6)* 7(PI8)* 8(PC13)* 9(PC14)* 10(PC15)* 11(PI9)* 12(PI10)* 13(PI11)* 16(PF0)* 17(PF1)* 18(PF2)* 19(PF3)* 20(PF4)* 21(PF5)* 24(PF6)* 25(PF7)* 26(PF8)* 27(PF9)* 28(PF10)* 30(PH1)* 32(PC0)* 33(PC1)* 34(PC2_C)* 35(PC3_C)* 41(PA1)* 42(PA2)* 43(PH2)* 44(PH3)* 45(PH4)* 46(PH5)* 47(PA3)* 50(PA4)* 51(PA5)* 52(PA6)* 53(PA7)* 54(PC4)* 55(PC5)* 56(PB0)* 57(PB1)* 58(PB2)* 59(PF11)* 60(PF12)* 63(PF13)* 64(PF14)* 65(PF15)* 66(PG0)* 67(PG1)* 68(PE7)* 69(PE8)* 70(PE9)* 73(PE10)* 74(PE11)* 75(PE12)* 76(PE13)* 77(PE14)* 78(PE15)* 83(PH6)* 84(PH7)* 85(PH8)* 86(PH9)* 87(PH10)* 88(PH11)* 89(PH12)* 98(PD10)* 99(PD11)* 100(PD12)* 101(PD13)* 104(PD14)* 105(PD15)* 106(PG2)* 107(PG3)* 108(PG4)* 109(PG5)* 110(PG6)* 111(PG7)* 112(PG8)* 115(PC6)* 116(PC7)* 117(PC8)* 118(PC9)* 119(PA8)* 122(PA11)* 123(PA12)* 128(PH13)* 129(PH14)* 130(PH15)* 131(PI0)* 132(PI1)* 133(PI2)* 134(PI3)* 138(PA15)* 139(PC10)* 140(PC11)* 141(PC12)* 144(PD2)* 145(PD3)* 146(PD4)* 151(PD7)* 152(PG9)* 153(PG10)* 154(PG11)* 155(PG12)* 156(PG13)* 157(PG14)* 160(PG15)* 162(PB4)* 163(PB5)* 164(PB6)* 165(PB7)* 167(PB8)* 168(PB9)* 169(PE0)* 170(PE1)* 173(PI4)* 174(PI5)* 175(PI6)* 176(PI7)*; Y1 1(TRI_STATE)*

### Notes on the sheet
- MCU_CORE — STM32H753IIT6
  P0 time capture pins remain fixed by PINMAP_SYS_001.csv

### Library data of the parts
#FLG0101 #FLG0103 = PWR_FLAG: hierarchy_path: /66980d89-56fb-4772-93a7-06a61d388399/531916ae-7957-4d09-a2e0-18a9c70f6c21
C10 C11 = C: MPN: 2.2uF_6.3V_X7R; hierarchy_path: /66980d89-56fb-4772-93a7-06a61d388399/531916ae-7957-4d09-a2e0-18a9c70f6c21
C12 = C: MPN: 4.7uF_6.3V_X7R; hierarchy_path: /66980d89-56fb-4772-93a7-06a61d388399/531916ae-7957-4d09-a2e0-18a9c70f6c21
C13 C15 = C: MPN: 100nF_6.3V_X7R; hierarchy_path: /66980d89-56fb-4772-93a7-06a61d388399/531916ae-7957-4d09-a2e0-18a9c70f6c21
C14 = C: MPN: 1uF_6.3V_X7R; hierarchy_path: /66980d89-56fb-4772-93a7-06a61d388399/531916ae-7957-4d09-a2e0-18a9c70f6c21
C100 = C: MPN: 100nF_6.3V_X7R; Decouples_U1_Pin: 15; hierarchy_path: /66980d89-56fb-4772-93a7-06a61d388399/531916ae-7957-4d09-a2e0-18a9c70f6c21
C101 = C: MPN: 100nF_6.3V_X7R; Decouples_U1_Pin: 23; hierarchy_path: /66980d89-56fb-4772-93a7-06a61d388399/531916ae-7957-4d09-a2e0-18a9c70f6c21
C102 = C: MPN: 100nF_6.3V_X7R; Decouples_U1_Pin: 36; hierarchy_path: /66980d89-56fb-4772-93a7-06a61d388399/531916ae-7957-4d09-a2e0-18a9c70f6c21
C103 = C: MPN: 100nF_6.3V_X7R; Decouples_U1_Pin: 49; hierarchy_path: /66980d89-56fb-4772-93a7-06a61d388399/531916ae-7957-4d09-a2e0-18a9c70f6c21
C104 = C: MPN: 100nF_6.3V_X7R; Decouples_U1_Pin: 62; hierarchy_path: /66980d89-56fb-4772-93a7-06a61d388399/531916ae-7957-4d09-a2e0-18a9c70f6c21
C105 = C: MPN: 100nF_6.3V_X7R; Decouples_U1_Pin: 72; hierarchy_path: /66980d89-56fb-4772-93a7-06a61d388399/531916ae-7957-4d09-a2e0-18a9c70f6c21
C106 = C: MPN: 100nF_6.3V_X7R; Decouples_U1_Pin: 82; hierarchy_path: /66980d89-56fb-4772-93a7-06a61d388399/531916ae-7957-4d09-a2e0-18a9c70f6c21
C107 = C: MPN: 100nF_6.3V_X7R; Decouples_U1_Pin: 91; hierarchy_path: /66980d89-56fb-4772-93a7-06a61d388399/531916ae-7957-4d09-a2e0-18a9c70f6c21
C108 = C: MPN: 100nF_6.3V_X7R; Decouples_U1_Pin: 103; hierarchy_path: /66980d89-56fb-4772-93a7-06a61d388399/531916ae-7957-4d09-a2e0-18a9c70f6c21
C109 = C: MPN: 100nF_6.3V_X7R; Decouples_U1_Pin: 127; hierarchy_path: /66980d89-56fb-4772-93a7-06a61d388399/531916ae-7957-4d09-a2e0-18a9c70f6c21
C110 = C: MPN: 100nF_6.3V_X7R; Decouples_U1_Pin: 136; hierarchy_path: /66980d89-56fb-4772-93a7-06a61d388399/531916ae-7957-4d09-a2e0-18a9c70f6c21
C111 = C: MPN: 100nF_6.3V_X7R; Decouples_U1_Pin: 149; hierarchy_path: /66980d89-56fb-4772-93a7-06a61d388399/531916ae-7957-4d09-a2e0-18a9c70f6c21
C112 = C: MPN: 100nF_6.3V_X7R; Decouples_U1_Pin: 159; hierarchy_path: /66980d89-56fb-4772-93a7-06a61d388399/531916ae-7957-4d09-a2e0-18a9c70f6c21
C113 = C: MPN: 100nF_6.3V_X7R; Decouples_U1_Pin: 172; hierarchy_path: /66980d89-56fb-4772-93a7-06a61d388399/531916ae-7957-4d09-a2e0-18a9c70f6c21
C114 = C: MPN: 100nF_6.3V_X7R; Decouples_U1_Pin: 114; hierarchy_path: /66980d89-56fb-4772-93a7-06a61d388399/531916ae-7957-4d09-a2e0-18a9c70f6c21
C115 = C: MPN: 100nF_6.3V_X7R; Filters_U1_Pin: 31; hierarchy_path: /66980d89-56fb-4772-93a7-06a61d388399/531916ae-7957-4d09-a2e0-18a9c70f6c21
FB1 = L_Ferrite: hierarchy_path: /66980d89-56fb-4772-93a7-06a61d388399/531916ae-7957-4d09-a2e0-18a9c70f6c21
J10 = Conn_01x06: MPN: TC2030-NL_TARGET; hierarchy_path: /66980d89-56fb-4772-93a7-06a61d388399/531916ae-7957-4d09-a2e0-18a9c70f6c21
R10 = R: MPN: 10k_1%; hierarchy_path: /66980d89-56fb-4772-93a7-06a61d388399/531916ae-7957-4d09-a2e0-18a9c70f6c21
TP1 TP2 = TestPoint: hierarchy_path: /66980d89-56fb-4772-93a7-06a61d388399/531916ae-7957-4d09-a2e0-18a9c70f6c21
U1 = STM32H753IITx: hierarchy_path: /66980d89-56fb-4772-93a7-06a61d388399/531916ae-7957-4d09-a2e0-18a9c70f6c21
Y1 = ECS-2520S33-250-FN-TR: Capture_Status: LOCAL_CONTRACT_SYMBOL; hierarchy_path: /66980d89-56fb-4772-93a7-06a61d388399/531916ae-7957-4d09-a2e0-18a9c70f6c21

## Sheet 30_TIME_GNSS.SchDoc
size 209 x 148 mm
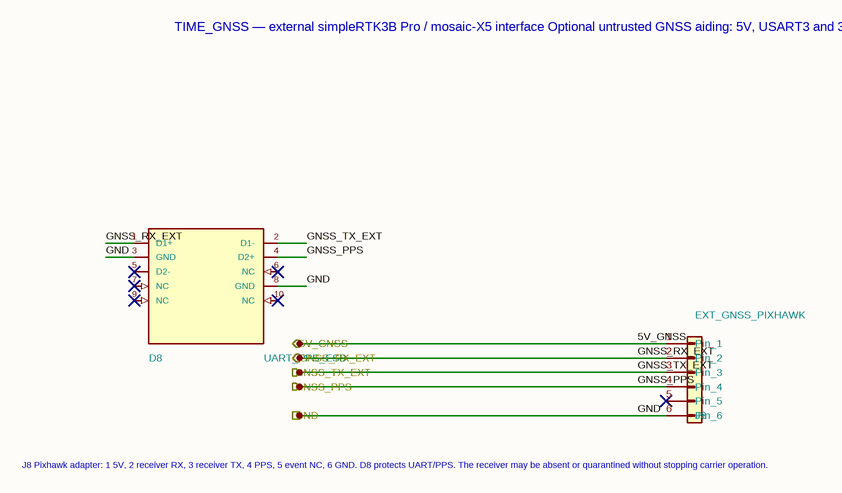
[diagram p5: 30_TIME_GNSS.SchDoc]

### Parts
D8  UART_PPS_ESD  [USON-10_2.5x1.0mm_P0.5mm]
J8  EXT_GNSS_PIXHAWK  [JST_GH_SM06B-GHS-TB_1x06-1MP_P1.25mm_Horizontal]

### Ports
5V_GNSS (in), GND, GNSS_PPS (out), GNSS_RX_EXT (in), GNSS_TX_EXT (out)

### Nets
5V_GNSS: J8.1(Pin_1) ; port 5V_GNSS
GND: D8.3(GND) D8.8(GND) J8.6(Pin_6) ; port GND
GNSS_PPS: D8.4(D2+) J8.4(Pin_4) ; port GNSS_PPS
GNSS_RX_EXT: D8.1(D1+) J8.2(Pin_2) ; port GNSS_RX_EXT
GNSS_TX_EXT: D8.2(D1-) J8.3(Pin_3) ; port GNSS_TX_EXT

Not connected (* = marked no-connect by the designer): D8 5(D2-)* 6(NC)* 7(NC)* 9(NC)* 10(NC)*; J8 5(Pin_5)*

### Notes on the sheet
- TIME_GNSS — external simpleRTK3B Pro / mosaic-X5 interface
  Optional untrusted GNSS aiding: 5V, USART3 and 3.3V PPS
- (near J8) J8 Pixhawk adapter: 1 5V, 2 receiver RX,
  3 receiver TX, 4 PPS, 5 event NC, 6 GND.
  D8 protects UART/PPS. The receiver may be absent
  or quarantined without stopping carrier operation.

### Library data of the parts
D8 = TPD4E05U06DQAR: Capture_Status: LOCAL_CONTRACT_SYMBOL; hierarchy_path: /66980d89-56fb-4772-93a7-06a61d388399/9c5f5607-c07c-4d34-adbd-36601c2debbf
J8 = Conn_01x06: MPN: SM06B-GHS-TB(LF)(SN); hierarchy_path: /66980d89-56fb-4772-93a7-06a61d388399/9c5f5607-c07c-4d34-adbd-36601c2debbf

## Sheet 40_IMU.SchDoc
size 209 x 148 mm
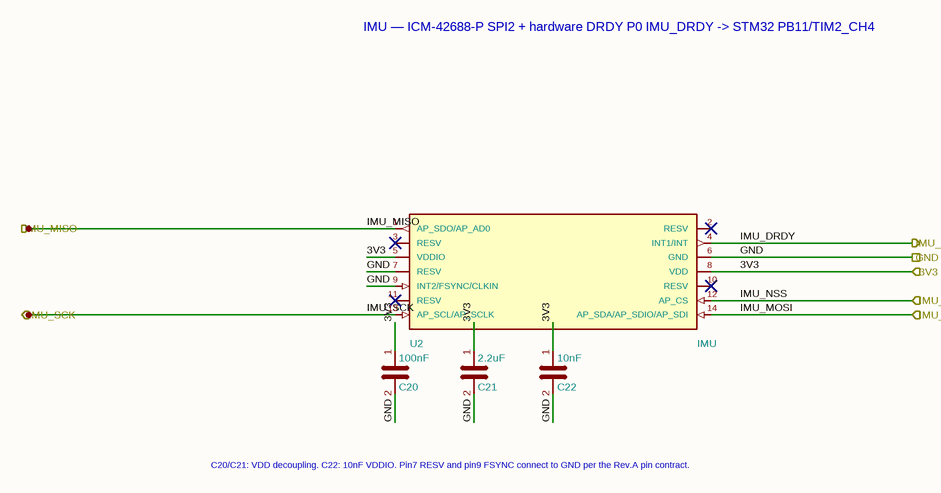
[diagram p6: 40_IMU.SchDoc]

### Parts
C20  100nF  [C_0402_1005Metric]
C21  2.2uF  [C_0603_1608Metric]
C22  10nF  [C_0402_1005Metric]
U2  IMU  [ICM-42688-P_LGA14_2.5x3mm_P0.5mm]

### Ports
3V3 (in), GND, IMU_DRDY (out), IMU_MISO (out), IMU_MOSI (in), IMU_NSS (in), IMU_SCK (in)

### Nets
3V3: C20.1 C21.1 C22.1 U2.5(VDDIO) U2.8(VDD) ; port 3V3
GND: C20.2 C21.2 C22.2 U2.6(GND) U2.7(RESV) U2.9(INT2/FSYNC/CLKIN) ; port GND
IMU_DRDY: U2.4(INT1/INT) ; port IMU_DRDY
IMU_MISO: U2.1(AP_SDO/AP_AD0) ; port IMU_MISO
IMU_MOSI: U2.14(AP_SDA/AP_SDIO/AP_SDI) ; port IMU_MOSI
IMU_NSS: U2.12(AP_CS) ; port IMU_NSS
IMU_SCK: U2.13(AP_SCL/AP_SCLK) ; port IMU_SCK

Not connected (* = marked no-connect by the designer): U2 2(RESV)* 3(RESV)* 10(RESV)* 11(RESV)*

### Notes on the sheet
- IMU — ICM-42688-P SPI2 + hardware DRDY
  P0 IMU_DRDY -> STM32 PB11/TIM2_CH4
- C20/C21: VDD decoupling. C22: 10nF VDDIO.
  Pin7 RESV and pin9 FSYNC connect to GND
  per the Rev.A pin contract.

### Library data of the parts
C20 = C: MPN: 100nF_6.3V_X7R; hierarchy_path: /66980d89-56fb-4772-93a7-06a61d388399/1152ce88-d77a-4f94-b3cb-08896bab9e7a
C21 = C: MPN: 2.2uF_6.3V_X7R; hierarchy_path: /66980d89-56fb-4772-93a7-06a61d388399/1152ce88-d77a-4f94-b3cb-08896bab9e7a
C22 = C: MPN: 10nF_6.3V_X7R; hierarchy_path: /66980d89-56fb-4772-93a7-06a61d388399/1152ce88-d77a-4f94-b3cb-08896bab9e7a
U2 = ICM-42688-P: Capture_Status: LOCAL_CONTRACT_SYMBOL; hierarchy_path: /66980d89-56fb-4772-93a7-06a61d388399/1152ce88-d77a-4f94-b3cb-08896bab9e7a

## Sheet 50_RADAR_IO_CAN.SchDoc
size 209 x 148 mm
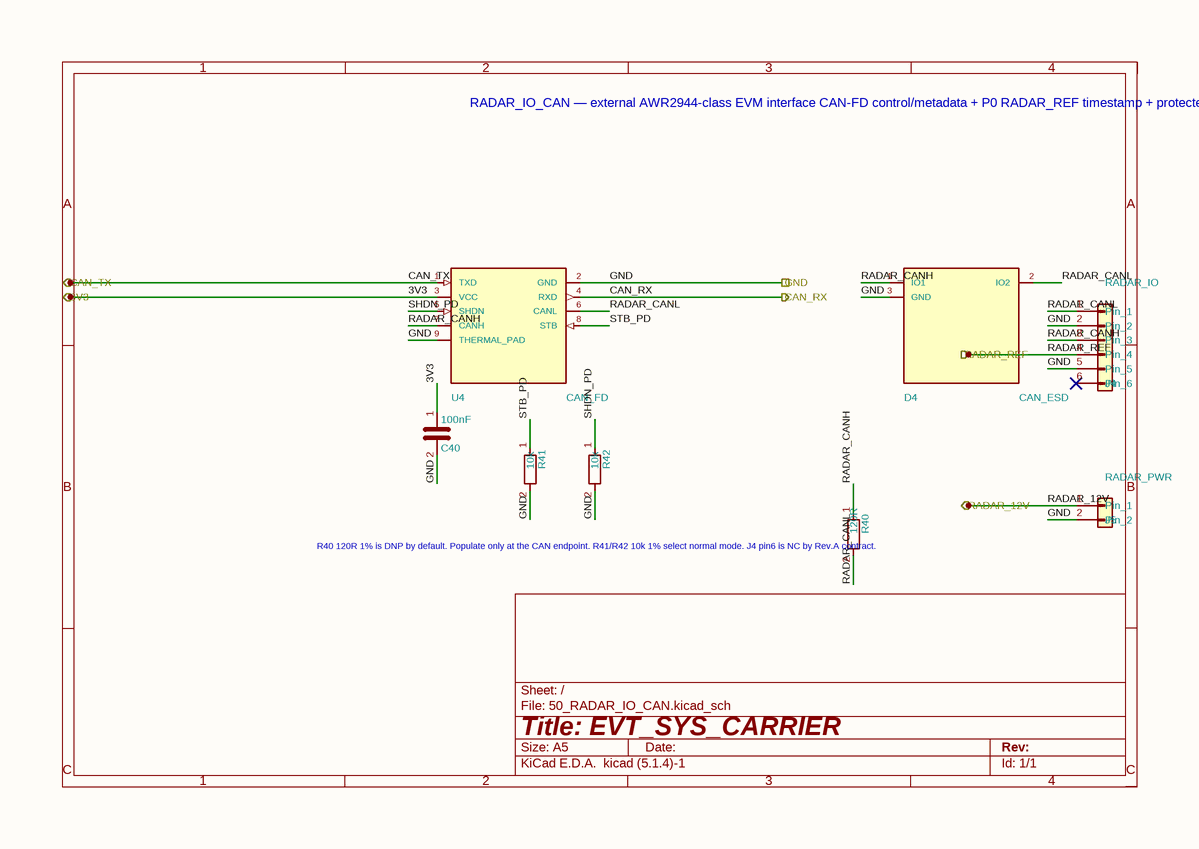
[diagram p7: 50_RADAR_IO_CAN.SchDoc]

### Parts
C40  100nF  [C_0402_1005Metric]
D4  CAN_ESD  [SOT-23]
J4  RADAR_IO  [Molex_43045-0600_RA_THT_6P]
J5  RADAR_PWR  [Molex_43650-0200_RA_THT_2P]
R40  120R  [R_0603_1608Metric]
R41  10k  [R_0603_1608Metric]
R42  10k  [R_0603_1608Metric]
U4  CAN_FD  [Texas_DRB0008A]

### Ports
3V3 (in), CAN_RX (out), CAN_TX (in), GND, RADAR_12V (in), RADAR_REF (out)

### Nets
3V3: C40.1 U4.3(VCC) ; port 3V3
CAN_RX: U4.4(RXD) ; port CAN_RX
CAN_TX: U4.1(TXD) ; port CAN_TX
GND: C40.2 D4.3(GND) J4.2(Pin_2) J4.5(Pin_5) J5.2(Pin_2) R41.2 R42.2 U4.2(GND) U4.9(THERMAL_PAD) ; port GND
RADAR_12V: J5.1(Pin_1) ; port RADAR_12V
RADAR_CANH: D4.1(IO1) J4.3(Pin_3) R40.1 U4.7(CANH)
RADAR_CANL: D4.2(IO2) J4.1(Pin_1) R40.2 U4.6(CANL)
RADAR_REF: J4.4(Pin_4) ; port RADAR_REF
SHDN_PD: R42.1 U4.5(SHDN)
STB_PD: R41.1 U4.8(STB)

Not connected (* = marked no-connect by the designer): J4 6(Pin_6)*

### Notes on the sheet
- RADAR_IO_CAN — external AWR2944-class EVM interface
  CAN-FD control/metadata + P0 RADAR_REF timestamp + protected 12V
- (near R40) R40 120R 1% is DNP by default.
  Populate only at the CAN endpoint.
  R41/R42 10k 1% select normal mode.
  J4 pin6 is NC by Rev.A contract.

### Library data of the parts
C40 = C: MPN: 100nF_6.3V_X7R; hierarchy_path: /66980d89-56fb-4772-93a7-06a61d388399/2b812d5a-90b0-498f-afec-462f55ab5efa
D4 = ESD2CANFD24DBZRQ1: Capture_Status: LOCAL_CONTRACT_SYMBOL; hierarchy_path: /66980d89-56fb-4772-93a7-06a61d388399/2b812d5a-90b0-498f-afec-462f55ab5efa
J4 = Conn_01x06: MPN: 43045-0600; hierarchy_path: /66980d89-56fb-4772-93a7-06a61d388399/2b812d5a-90b0-498f-afec-462f55ab5efa
J5 = Conn_01x02: MPN: 43650-0200; hierarchy_path: /66980d89-56fb-4772-93a7-06a61d388399/2b812d5a-90b0-498f-afec-462f55ab5efa
R40 = R: MPN: 120R_1%; hierarchy_path: /66980d89-56fb-4772-93a7-06a61d388399/2b812d5a-90b0-498f-afec-462f55ab5efa
R41 R42 = R: MPN: 10k_1%; hierarchy_path: /66980d89-56fb-4772-93a7-06a61d388399/2b812d5a-90b0-498f-afec-462f55ab5efa
U4 = TCAN3404DRBRQ1: Capture_Status: LOCAL_CONTRACT_SYMBOL; hierarchy_path: /66980d89-56fb-4772-93a7-06a61d388399/2b812d5a-90b0-498f-afec-462f55ab5efa

## Sheet 60_HOST_UART.SchDoc
size 209 x 148 mm
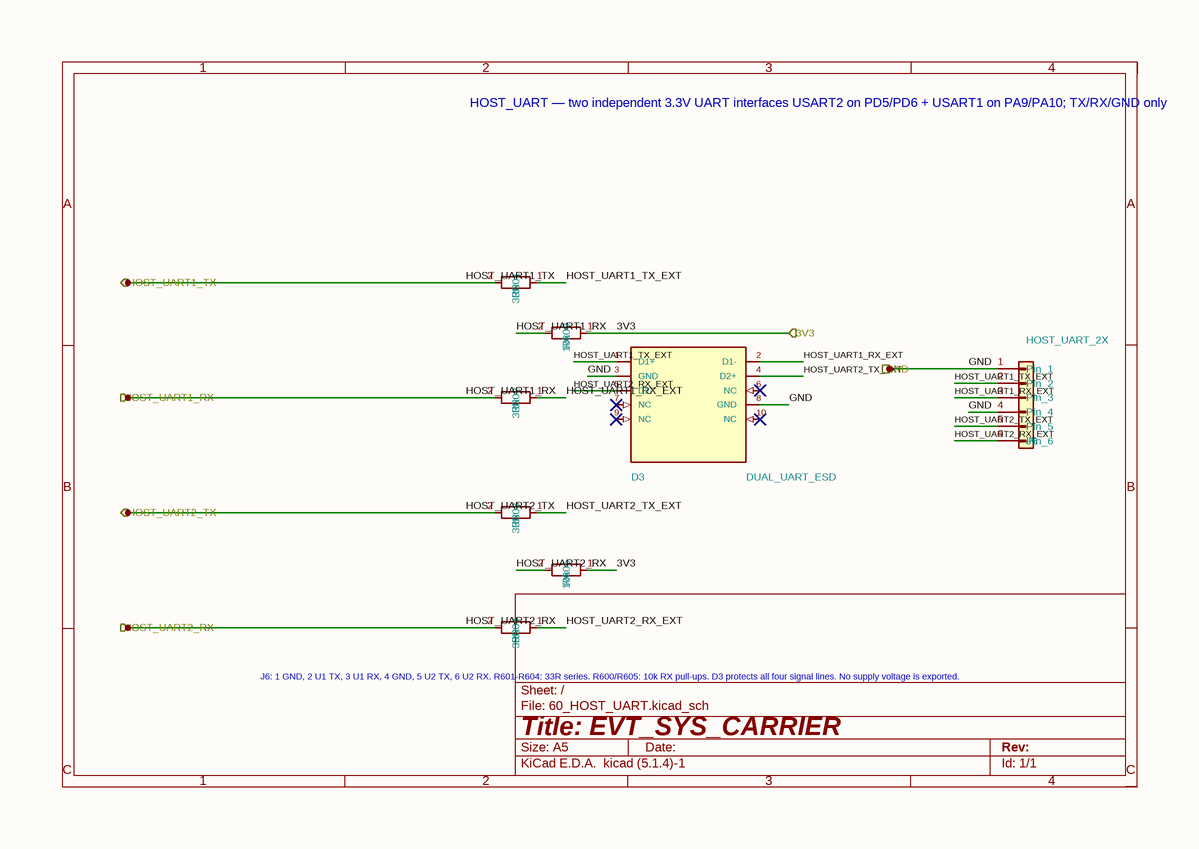
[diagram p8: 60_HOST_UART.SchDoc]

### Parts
D3  DUAL_UART_ESD  [USON-10_2.5x1.0mm_P0.5mm]
J6  HOST_UART_2X  [Molex_43045-0600_RA_THT_6P]
R600  10k  [R_0603_1608Metric]
R601  33R  [R_0402_1005Metric]
R602  33R  [R_0402_1005Metric]
R603  33R  [R_0402_1005Metric]
R604  33R  [R_0402_1005Metric]
R605  10k  [R_0603_1608Metric]

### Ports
3V3 (in), GND, HOST_UART1_RX (out), HOST_UART1_TX (in), HOST_UART2_RX (out), HOST_UART2_TX (in)

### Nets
3V3: R600.1 R605.1 ; port 3V3
GND: D3.3(GND) D3.8(GND) J6.1(Pin_1) J6.4(Pin_4) ; port GND
HOST_UART1_RX: R600.2 R602.2 ; port HOST_UART1_RX
HOST_UART1_RX_EXT: D3.2(D1-) J6.3(Pin_3) R602.1
HOST_UART1_TX: R601.2 ; port HOST_UART1_TX
HOST_UART1_TX_EXT: D3.1(D1+) J6.2(Pin_2) R601.1
HOST_UART2_RX: R604.2 R605.2 ; port HOST_UART2_RX
HOST_UART2_RX_EXT: D3.5(D2-) J6.6(Pin_6) R604.1
HOST_UART2_TX: R603.2 ; port HOST_UART2_TX
HOST_UART2_TX_EXT: D3.4(D2+) J6.5(Pin_5) R603.1

Not connected (* = marked no-connect by the designer): D3 6(NC)* 7(NC)* 9(NC)* 10(NC)*

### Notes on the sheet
- HOST_UART — two independent 3.3V UART interfaces
  USART2 on PD5/PD6 + USART1 on PA9/PA10; TX/RX/GND only
- (near R604) J6: 1 GND, 2 U1 TX, 3 U1 RX,
  4 GND, 5 U2 TX, 6 U2 RX.
  R601-R604: 33R series. R600/R605: 10k RX pull-ups.
  D3 protects all four signal lines.
  No supply voltage is exported.

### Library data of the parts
D3 = TPD4E05U06DQAR: Capture_Status: LOCAL_CONTRACT_SYMBOL; hierarchy_path: /66980d89-56fb-4772-93a7-06a61d388399/8d70ae48-bcdc-481f-a052-a7c6b659cbf0
J6 = Conn_01x06: MPN: 43045-0600; hierarchy_path: /66980d89-56fb-4772-93a7-06a61d388399/8d70ae48-bcdc-481f-a052-a7c6b659cbf0
R600 R605 = R: MPN: 10k_1%; hierarchy_path: /66980d89-56fb-4772-93a7-06a61d388399/8d70ae48-bcdc-481f-a052-a7c6b659cbf0
R601-R604 = R: MPN: 33R_1%; hierarchy_path: /66980d89-56fb-4772-93a7-06a61d388399/8d70ae48-bcdc-481f-a052-a7c6b659cbf0

## Sheet 70_DEBUG_BOOT.SchDoc
size 209 x 148 mm
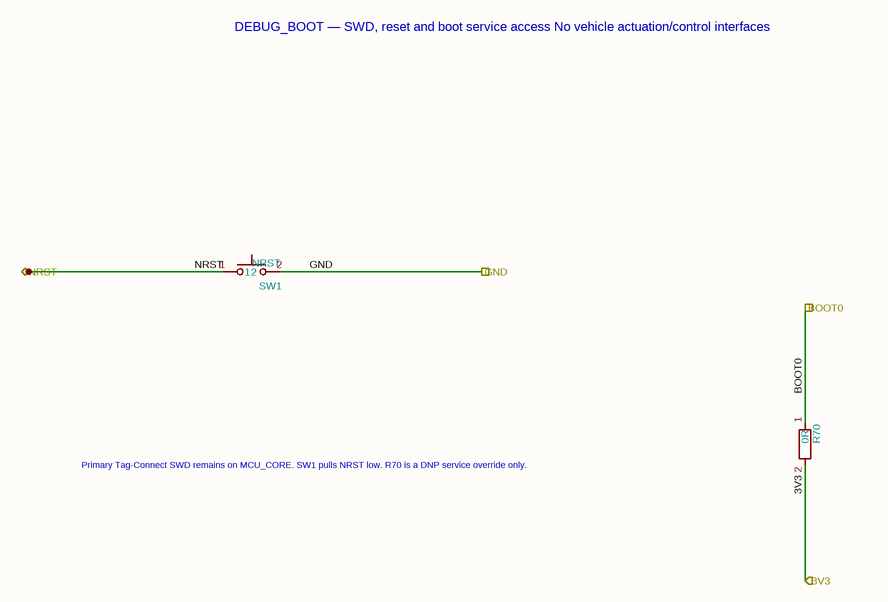
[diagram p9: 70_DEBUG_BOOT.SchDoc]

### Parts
R70  0R  [R_0603_1608Metric]
SW1  NRST  [ESwitch_TL3301_GullWing_6x6]

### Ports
3V3 (in), BOOT0, GND, NRST (bidir)

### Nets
3V3: R70.2 ; port 3V3
BOOT0: R70.1 ; port BOOT0
GND: SW1.2 ; port GND
NRST: SW1.1 ; port NRST

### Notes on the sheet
- DEBUG_BOOT — SWD, reset and boot service access
  No vehicle actuation/control interfaces
- Primary Tag-Connect SWD remains on MCU_CORE.
  SW1 pulls NRST low. R70 is a DNP
  service override only.

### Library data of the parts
R70 = R: hierarchy_path: /66980d89-56fb-4772-93a7-06a61d388399/3686b07d-3d02-4fcb-be66-106e5ebdc9c7
SW1 = SW_Push: MPN: TL3301NF160QG; hierarchy_path: /66980d89-56fb-4772-93a7-06a61d388399/3686b07d-3d02-4fcb-be66-106e5ebdc9c7

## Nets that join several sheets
3V3: 10_POWER_INPUT (7 pins), 20_MCU_CORE (38 pins), 40_IMU (5 pins), 50_RADAR_IO_CAN (C40.1 U4.3), 60_HOST_UART (R600.1 R605.1), 70_DEBUG_BOOT (R70.2)
5V_GNSS: 10_POWER_INPUT (C91.1 L9.2 R90.2 U9.14), 30_TIME_GNSS (J8.1)
BOOT0: 20_MCU_CORE (R10.1 U1.166), 70_DEBUG_BOOT (R70.1)
CAN_RX: 20_MCU_CORE (U1.142), 50_RADAR_IO_CAN (U4.4)
CAN_TX: 20_MCU_CORE (U1.143), 50_RADAR_IO_CAN (U4.1)
GND: 10_POWER_INPUT (57 pins), 20_MCU_CORE (39 pins), 30_TIME_GNSS (D8.3 D8.8 J8.6), 40_IMU (6 pins), 50_RADAR_IO_CAN (9 pins), 60_HOST_UART (D3.3 D3.8 J6.1 J6.4), 70_DEBUG_BOOT (SW1.2)
GNSS_PPS: 20_MCU_CORE (U1.40), 30_TIME_GNSS (D8.4 J8.4)
GNSS_RX_EXT: 20_MCU_CORE (U1.96), 30_TIME_GNSS (D8.1 J8.2)
GNSS_TX_EXT: 20_MCU_CORE (U1.97), 30_TIME_GNSS (D8.2 J8.3)
HOST_UART1_RX: 20_MCU_CORE (TP2.1 U1.150), 60_HOST_UART (R600.2 R602.2)
HOST_UART1_TX: 20_MCU_CORE (TP1.1 U1.147), 60_HOST_UART (R601.2)
HOST_UART2_RX: 20_MCU_CORE (U1.121), 60_HOST_UART (R604.2 R605.2)
HOST_UART2_TX: 20_MCU_CORE (U1.120), 60_HOST_UART (R603.2)
IMU_DRDY: 20_MCU_CORE (U1.80), 40_IMU (U2.4)
IMU_MISO: 20_MCU_CORE (U1.94), 40_IMU (U2.1)
IMU_MOSI: 20_MCU_CORE (U1.95), 40_IMU (U2.14)
IMU_NSS: 20_MCU_CORE (U1.92), 40_IMU (U2.12)
IMU_SCK: 20_MCU_CORE (U1.93), 40_IMU (U2.13)
NRST: 20_MCU_CORE (C115.1 U1.31), 70_DEBUG_BOOT (SW1.1)
RADAR_12V: 10_POWER_INPUT (U7.6), 50_RADAR_IO_CAN (J5.1)
RADAR_EFUSE_FLT: 10_POWER_INPUT (R7F.1 U7.4), 20_MCU_CORE (U1.2)
RADAR_REF: 20_MCU_CORE (U1.79), 50_RADAR_IO_CAN (J4.4)
SYS_EFUSE_FLT: 10_POWER_INPUT (R6F.1 U6.14), 20_MCU_CORE (U1.1)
